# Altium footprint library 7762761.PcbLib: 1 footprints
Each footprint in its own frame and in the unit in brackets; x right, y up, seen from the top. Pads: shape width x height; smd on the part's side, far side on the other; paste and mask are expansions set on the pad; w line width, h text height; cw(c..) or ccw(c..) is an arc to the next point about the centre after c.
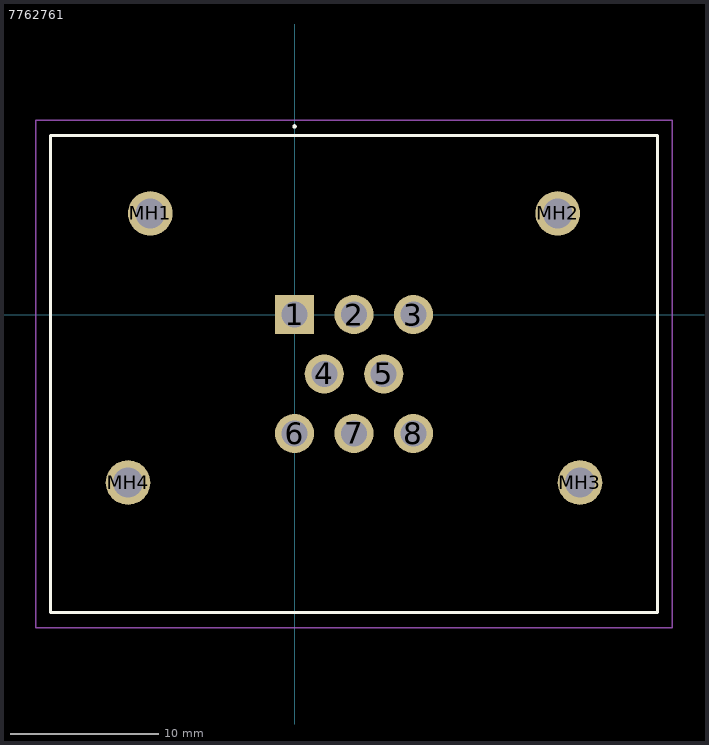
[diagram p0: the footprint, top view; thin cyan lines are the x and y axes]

## 7762761 [mm]
pads (12):
  rect 2.625x2.625 hole 1.75: 1(0,0)
  round 2.625 hole 1.75: 2(4,0) 3(8,0) 4(2,-4) 5(6,-4) 6(0,-8) 7(4,-8) 8(8,-8)
  round 3 hole 2: MH1(-9.7,6.8) MH2(17.7,6.8) MH3(19.2,-11.3) MH4(-11.2,-11.3)
Top Overlay:
  lines w0.2: 0,12.6 cw(c0,12.65) 0,12.7 ; 0,12.6 0,12.6 ; 0,12.6 ccw(c0,12.65) 0,12.7 ; 0,12.6 cw(c0,12.65) 0,12.7 ; 0,12.7 0,12.7 ; 0,12.7 0,12.7 ; -16.4,-20.05 24.4,-20.05 24.4,12.05 -16.4,12.05 -16.4,-20.05
Mechanical 15:
  lines w0.1: -16.4,-20.05 24.4,-20.05 24.4,12.05 -16.4,12.05 -16.4,-20.05
Mechanical 20:
  lines w0.1: -17.4,-21.05 25.4,-21.05 25.4,13.05 -17.4,13.05 -17.4,-21.05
